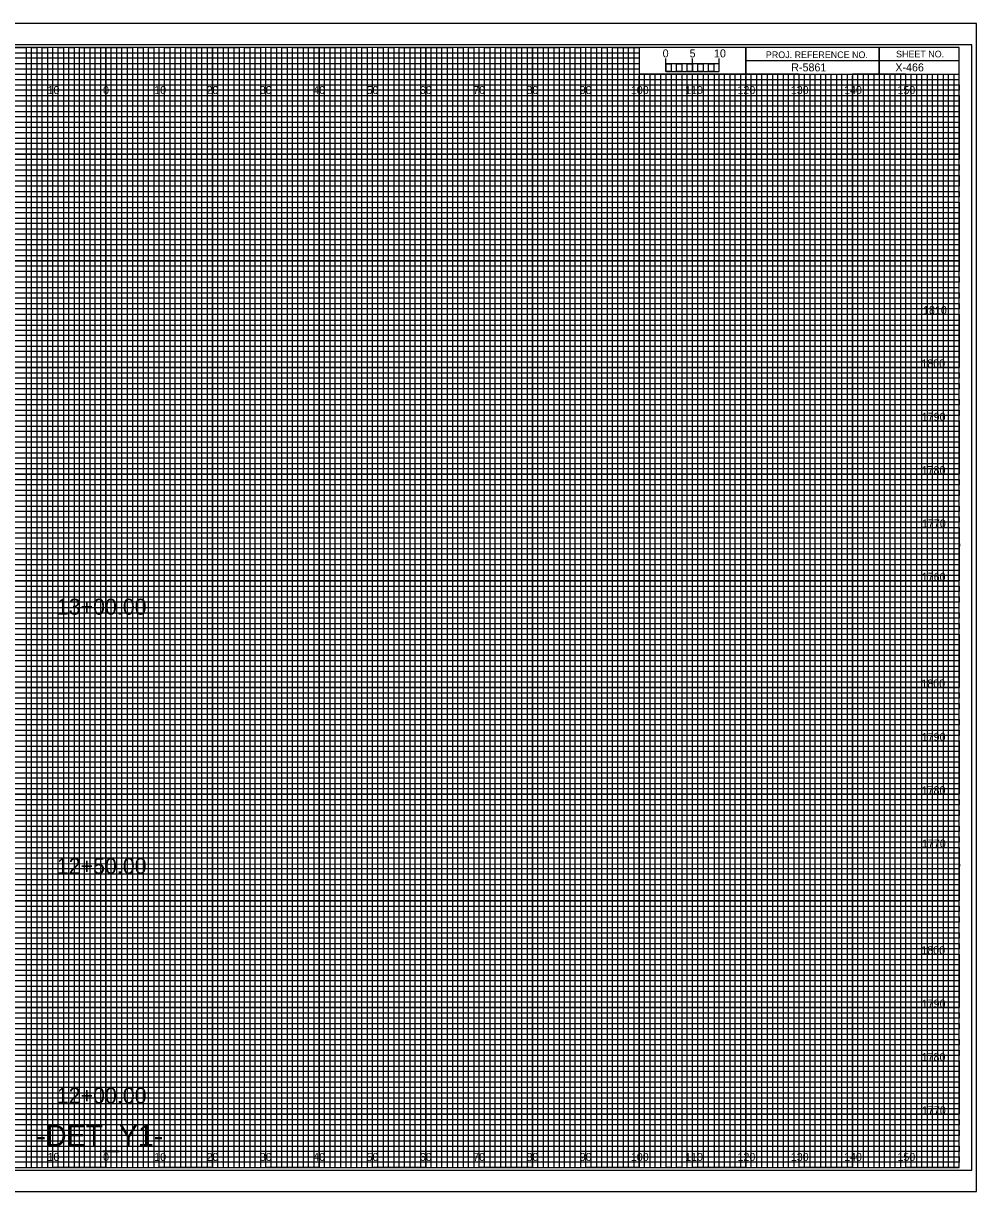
# Model space of a CAD drawing. Extents: x -13 to 323, y -5 to 434.
# Drawn here: x 144.5 to 323.3, y 215.5 to 434.5 of the extents above; entities that cross this region are included whole.
import ezdxf

# ---------------------------------------------------------------- set-up
doc = ezdxf.new("R2010")
doc.units = 0
for name, color, linetype in [('Old_Level_1', 7, 'Continuous'), ('Old_Level_62', 7, 'Continuous'), ('Pattern 1', 7, 'Continuous'), ('Pattern 18', 7, 'Continuous'), ('Pattern 4', 7, 'Continuous'), ('Pattern 5', 7, 'Continuous'), ('Prop Dimension', 7, 'Continuous'), ('Prop Horizontal Alignment', 7, 'Continuous'), ('Prop PHM Label Text', 7, 'Continuous'), ('Prop PHM Label Text White', 7, 'Continuous'), ('Prop PHM Roadway Shape', 7, 'Continuous'), ('Prop PHM White Shape', 7, 'Continuous'), ('Scratch_Level_0', 7, 'Continuous'), ('Scratch_Level_2', 7, 'Continuous'), ('Scratch_Level_3', 7, 'Continuous'), ('Scratch_Level_5', 7, 'Continuous'), ('Scratch_Level_6', 7, 'Continuous')]:
    doc.layers.add(name, color=color, linetype=linetype)

msp = doc.modelspace()

# ---------------------------------------------------------------- linework, layer by layer
at = {"layer": 'Old_Level_62'}
for p, q in [((0, 429), (260, 429)), ((260, 427.98), (0, 427.98)), ((260, 429), (260, 427.98)), ((0, 427), (260, 427)), ((260, 425.89), (0, 425.89)), ((260, 427), (260, 425.89)), ((0, 424), (320, 424))]:
    msp.add_line(p, q, dxfattribs=at)
for points in [[(0, 423), (270, 423), (320, 423), (320, 422), (0, 422)], [(0, 421), (320, 421), (320, 419), (0, 419)], [(0, 418), (320, 418), (320, 417), (0, 416.98)], [(0, 416), (320, 416), (320, 414), (0, 414)], [(0, 413), (320, 413), (320, 412), (0, 412)], [(0, 411), (320, 411), (320, 409), (0, 409)], [(0, 408), (320, 408), (320, 407), (0, 407)], [(0, 406), (320, 406), (320, 404), (0, 404)], [(0, 403), (320, 403), (320, 402), (0, 402)], [(0, 401), (320, 401), (320, 399), (0, 399)], [(0, 398), (320, 398), (320, 397), (0, 397)], [(0, 396), (320, 396), (320, 393.95), (320, 393), (320, 392), (0, 392)], [(0, 394), (320, 394), (320, 393), (0, 393)], [(0, 391), (320, 391), (320, 389), (0, 389.03)], [(0, 389.03), (320, 389), (320, 388), (0, 388)], [(0, 387), (320, 387), (320, 386), (0, 386)], [(0, 384), (320, 384), (320, 383), (0, 383)], [(0, 382), (320, 382), (320, 381), (0, 381)], [(-0.07, 378.89), (320, 378.89), (320, 377.88), (-0.07, 377.88)], [(0, 377), (320, 377), (320, 376), (0, 376)], [(0, 374), (320, 374), (320, 373), (0, 373)], [(0, 372), (320, 372), (320, 371), (0, 371)], [(0, 369), (320, 369), (320, 368), (0, 368)], [(0, 367), (320, 367), (320, 366), (0, 366)], [(0, 364), (320, 364), (320, 363), (0, 363)], [(0, 362), (320, 362), (320, 361), (0, 361)], [(0, 359), (320, 359), (319.99, 357.98), (0, 358)], [(0, 357), (320, 357), (320, 356), (0, 356)], [(0, 354), (320, 354), (320, 353), (0, 353)], [(0, 352), (320, 352), (320, 351), (0, 351)], [(0, 349), (320, 349), (320, 348), (0, 348)], [(0, 347), (320, 347), (320, 346), (0, 346)], [(0, 344), (320, 344), (320, 343), (0, 343)], [(0, 342), (320, 342), (320, 341), (0, 341)], [(0, 339), (320, 339), (320, 338), (0, 338)], [(0, 336.99), (320.07, 336.91), (320, 336), (0, 336)], [(0, 334), (320, 334), (320, 333), (0, 333)], [(0, 332), (320, 332), (320, 331), (0, 331)], [(0, 329), (320, 329), (320, 328), (0, 328)], [(0, 327), (320, 327), (320, 326), (0, 326)], [(0, 324), (320, 324), (320, 323), (0, 323)], [(0, 322), (320, 322), (320, 321), (0, 321)], [(0, 319), (320, 319), (320, 318), (0, 318)], [(0, 317), (320, 317), (320, 316), (0, 316)], [(0, 314), (320, 314), (320, 313), (0, 313)], [(0, 312), (320, 312), (320, 311), (0, 311)], [(0, 309), (320, 309), (320, 308), (0, 308)], [(0, 307), (320, 307), (320, 306), (0, 306)], [(0, 304), (320, 304), (320, 303), (0, 303)], [(0, 302), (320, 302), (320, 301), (0, 301)], [(0, 299), (320, 299), (319.99, 297.98), (0, 298)], [(0, 297), (320, 297), (320, 296), (0, 296)], [(0, 294), (320, 294), (320, 293), (0, 293)], [(0, 292), (320, 292), (320, 291), (0, 291)], [(0, 289), (320, 289), (320, 288), (0, 288)], [(0, 287), (320, 287), (320, 286), (0, 286)], [(0, 284), (320, 284), (320, 283), (0, 283)], [(0, 282), (320, 282), (320, 281), (0, 281)], [(0, 279), (320, 279), (320, 278), (0, 278)], [(0, 276.99), (320.07, 276.91), (320, 276), (0, 276)], [(0, 274), (320, 274), (320, 273), (0, 273)], [(0, 272), (320, 272), (320, 271), (0, 271)], [(0, 269), (320, 269), (320, 268), (0, 268)], [(0, 267), (320, 267), (320, 266), (0, 266)], [(0, 264), (320, 264), (320, 263), (0, 263)], [(0, 262), (320, 262), (320, 261), (0, 261)], [(0, 259), (320, 259), (320, 258), (0, 258)], [(0, 257), (320, 257), (320, 256), (0, 256)], [(0, 254), (320, 254), (320, 253), (0, 253)], [(0, 252), (320, 252), (320, 251), (0, 251)], [(0, 249), (320, 249), (320, 248), (0, 248)], [(0, 247), (320, 247), (320, 246), (0, 246)], [(0, 244), (320, 244), (320, 243), (0, 243)], [(0, 242), (320, 242), (320, 241), (0, 241)], [(0, 239), (320, 239), (320, 238), (0, 238)], [(0, 237), (320, 237), (320, 236), (0, 236)], [(0, 234), (320, 234), (320, 233), (0, 233)], [(0, 232), (320, 232), (320, 231), (0, 231)], [(0, 229), (320, 229), (320, 228), (0, 228)], [(0, 227), (320, 227), (320, 226), (0, 226)], [(0, 224), (320, 224), (320, 223), (0, 223)], [(0, 222), (320, 222), (320, 221), (0, 221)]]:
    msp.add_lwpolyline(points, dxfattribs=at)
at = {"layer": 'Pattern 1'}
for p, q in [((323.3, 434.5), (-13.4, 434.5)), ((-13.4, 215.5), (323.3, 215.5))]:
    msp.add_line(p, q, dxfattribs=at)
at = {"layer": 'Pattern 18'}
for p, q in [((265, 425.49), (265, 427.9)), ((265, 426.9), (265, 427.9)), ((270, 425.49), (270, 427.9)), ((275, 425.49), (275, 427.9)), ((275, 426.9), (275, 427.9))]:
    msp.add_line(p, q, dxfattribs=at)
for points in [[(275, 426.9), (265, 426.9), (265, 425.49), (275, 425.49)], [(265, 426.9), (266, 426.9), (266, 425.49), (265, 425.49)], [(267, 426.9), (268, 426.9), (268, 425.49), (267, 425.49)], [(269, 426.9), (270, 426.9), (270, 425.49), (269, 425.49)], [(271, 426.9), (272, 426.9), (272, 425.49), (271, 425.49)], [(273, 426.9), (274, 426.9), (274, 425.49), (273, 425.49)]]:
    msp.add_lwpolyline(points, close=True, dxfattribs=at)
at = {"layer": 'Pattern 4'}
for points in [[(135, 430), (145, 430), (145, 220), (155, 220), (155, 430), (165, 430), (165, 220), (175, 220), (175, 430), (185, 430), (185, 220), (195, 220), (195, 430), (205, 430), (205, 220), (215, 220), (215, 430), (225, 430), (225, 220), (235, 220), (235, 430), (245, 430), (245, 220), (255, 220), (255, 430), (259.93, 430), (260, 430), (260, 425), (264.99, 425), (264.99, 220), (275, 220), (275, 425), (285, 425), (285, 220), (295, 220), (295, 425), (305, 425), (305, 220), (315, 220), (315, 425)], [(0, 425), (275, 425)], [(0, 405), (320, 405), (320, 415), (0, 415)], [(0, 385), (320, 385), (320, 395), (0, 395)], [(0, 365), (320, 365), (320, 375), (0, 375)], [(0, 345), (320, 345), (320, 355), (0, 355)], [(0, 325), (320, 325), (320, 335), (0, 335)], [(0, 305), (320, 305), (320, 315), (0, 315)], [(0, 285), (320, 285), (320, 295), (0, 295)], [(0, 265), (320, 265), (320, 275), (0, 275)], [(0, 245), (320, 245), (320, 255), (0, 255)], [(0, 225), (320, 225), (320, 235), (0, 235)]]:
    msp.add_lwpolyline(points, dxfattribs=at)
at = {"layer": 'Pattern 5'}
for p, q in [((150, 220), (150, 430)), ((160, 220), (160, 430)), ((170, 220), (170, 430)), ((180, 220), (180, 430)), ((190, 220), (190, 430)), ((200, 220), (200, 430)), ((210, 220), (210, 430)), ((220, 220), (220, 430)), ((230, 220), (230, 430)), ((240, 220), (240, 430)), ((250, 220), (250, 430)), ((260, 220), (260, 424.69)), ((270, 220), (270, 424.69)), ((280, 220), (280, 424.69)), ((290, 220), (290, 424.69)), ((300, 220), (300, 424.69)), ((310, 220), (310, 424.69)), ((0, 420), (320, 420)), ((0, 410), (320, 410)), ((0, 400), (320, 400)), ((0, 390), (320, 390)), ((0, 380), (320, 380)), ((0, 370), (320, 370)), ((0, 360), (320, 360)), ((0, 350), (320, 350)), ((0, 340), (320, 340)), ((0, 330), (320, 330)), ((0, 320), (320, 320)), ((0, 310), (320, 310)), ((0, 300), (320, 300)), ((0, 290), (320, 290)), ((0, 280), (320, 280)), ((0, 270), (320, 270)), ((0, 260), (320, 260)), ((0, 250), (320, 250)), ((0, 240), (320, 240)), ((0, 230), (320, 230))]:
    msp.add_line(p, q, dxfattribs=at)
at = {"layer": 'Prop Dimension'}
for p, q in [((305, 430), (305, 425)), ((305, 425), (305, 430)), ((280, 427.5), (280, 425)), ((320, 427.49), (280, 427.49)), ((280, 425), (320, 425))]:
    msp.add_line(p, q, dxfattribs=at)
for points in [[(320, 430), (0, 430), (0, 220), (320, 220)], [(280, 430), (260, 430), (260, 425.03), (280, 425.03)], [(320, 430), (280, 430), (280, 425), (320, 425)]]:
    msp.add_lwpolyline(points, close=True, dxfattribs=at)
at = {"layer": 'Prop Horizontal Alignment'}
for p, q in [((150, 430), (140, 430)), ((150, 220), (150, 430)), ((170, 430), (160, 430)), ((160, 430), (160, 220)), ((170, 220), (170, 430)), ((190, 430), (180, 430)), ((180, 430), (180, 220)), ((190, 220), (190, 430)), ((210, 430), (200, 430)), ((200, 430), (200, 220)), ((210, 220), (210, 430)), ((230, 430), (220, 430)), ((220, 430), (220, 220)), ((230, 220), (230, 430)), ((250, 430), (240, 430)), ((240, 430), (240, 220)), ((250, 220), (250, 430)), ((260, 430), (260, 220)), ((270, 220), (270, 425)), ((290, 425), (280, 425)), ((280, 425), (280, 220)), ((290, 220), (290, 425)), ((310, 425), (300, 425)), ((300, 425), (300, 220)), ((310, 220), (310, 425)), ((160, 220), (150, 220)), ((180, 220), (170, 220)), ((200, 220), (190, 220)), ((220, 220), (210, 220)), ((240, 220), (230, 220)), ((260, 220), (250, 220)), ((280, 220), (270, 220)), ((300, 220), (290, 220)), ((320, 220), (310, 220)), ((320, 220), (320, 220))]:
    msp.add_line(p, q, dxfattribs=at)
for points in [[(0, 420), (320, 420), (320, 410), (0, 410)], [(0, 400), (320, 400), (320, 390), (0, 390)], [(0, 380), (320, 380), (320, 370), (0, 370)], [(0, 360), (320, 360), (320, 350), (0, 350)], [(0, 340), (320, 340), (320, 330), (0, 330)], [(0, 320), (320, 320), (320, 310), (0, 310)], [(0, 300), (320, 300), (320, 290), (0, 290)], [(0, 280), (320, 280), (320, 270), (0, 270)], [(0, 260), (320, 260), (320, 250), (0, 250)], [(0, 240), (320, 240), (320, 230), (0, 230)]]:
    msp.add_lwpolyline(points, dxfattribs=at)
at = {"layer": 'Prop PHM Label Text'}
for p, q in [((267, 425), (266.01, 425)), ((266.01, 425), (266.01, 220)), ((267, 220), (267, 425)), ((269, 425), (268, 425)), ((268, 425), (268, 220)), ((269, 220), (269, 425)), ((266.01, 220), (265, 220)), ((268, 220), (267, 220))]:
    msp.add_line(p, q, dxfattribs=at)
for points in [[(145, 220), (146, 220), (146, 430), (147, 430), (147, 220)], [(147, 220), (148, 220), (148, 430), (149, 430), (149, 220)], [(150, 220), (151, 220), (151, 430), (152, 430), (152, 220)], [(152, 220), (153, 220), (153, 430), (154, 430), (154, 220)], [(155, 220), (156, 220), (156, 430), (157, 430), (157, 220)], [(157, 220), (158, 220), (158, 430), (159, 430), (159, 220)], [(160, 220), (161, 220), (161, 430), (162, 430), (162, 220)], [(162, 220), (163, 220), (163, 430), (164, 430), (164, 220)], [(165, 220), (166, 220), (166, 430), (167, 430), (167, 220)], [(167, 220), (168, 220), (168, 430), (169, 430), (169, 220)], [(170, 220), (171, 220), (171, 430), (172, 430), (172, 220)], [(172, 220), (173, 220), (173, 430), (174, 430), (174, 220)], [(175, 220), (176, 220), (176, 430), (177, 430), (177, 220)], [(177, 220), (178, 220), (178, 430), (179, 430), (179, 220)], [(180, 220), (181, 220), (181, 430), (182, 430), (182, 220)], [(182, 220), (183, 220), (183, 430), (184, 430), (184, 220)], [(185, 220), (186, 220), (186, 430), (187, 430), (187, 220)], [(187, 220), (188, 220), (188, 430), (189, 430), (189, 220)], [(190, 220), (191, 220), (191, 430), (192, 430), (192, 220)], [(192, 220), (193, 220), (193, 430), (194, 430), (194, 220)], [(195, 220), (196, 220), (196, 430), (197, 430), (197, 220)], [(197, 220), (198, 220), (198, 430), (199, 430), (199, 220)], [(200, 220), (201, 220), (201, 430), (202, 430), (202, 220)], [(202, 220), (203, 220), (203, 430), (204, 430), (204, 220)], [(205, 220), (206, 220), (206, 430), (207, 430), (207, 220)], [(207, 220), (208, 220), (208, 430), (209, 430), (209, 220)], [(210, 220), (211, 220), (211, 430), (212, 430), (212, 220)], [(212, 220), (213, 220), (213, 430), (214, 430), (214, 220)], [(215, 220), (216, 220), (216, 430), (217, 430), (217, 220)], [(217, 220), (218, 220), (218, 430), (219, 430), (219, 220)], [(220, 220), (221, 220), (221, 430), (222, 430), (222, 220)], [(222, 220), (223, 220), (223, 430), (224, 430), (224, 220)], [(225, 220), (226, 220), (226, 430), (227, 430), (227, 220)], [(227, 220), (228, 220), (228, 430), (229, 430), (229, 220)], [(230, 220), (231, 220), (231, 430), (232, 430), (232, 220)], [(232, 220), (233, 220), (233, 430), (234, 430), (234, 220)], [(235, 220), (236, 220), (236, 430), (237, 430), (237, 220)], [(237, 220), (238, 220), (238, 430), (239, 430), (239, 220)], [(240, 220), (241, 220), (241, 430), (242, 430), (242, 220)], [(242, 220), (243, 220), (243, 430), (244, 430), (244, 220)], [(245, 220), (246, 220), (246, 430), (247, 430), (247, 220)], [(247, 220), (248, 220), (248, 430), (249, 430), (249, 220)], [(250, 220), (251, 220), (251, 430), (252, 430), (252, 220)], [(252, 220), (253, 220), (253, 430), (254, 430), (254, 220)], [(255, 220), (256, 220), (256, 430), (257, 430), (257, 220)], [(257, 220), (258, 220), (258, 430), (259, 430), (259, 220)], [(260, 220), (261, 220), (261, 425), (262.02, 425), (262.02, 220)], [(262, 220), (263, 220), (263, 425), (263.99, 425), (263.99, 220)], [(270, 220), (270.98, 220), (270.98, 425), (272, 425), (272, 220)], [(272, 220), (273, 220), (273, 425), (274.05, 425), (274.05, 220)], [(275, 220), (276, 220), (276, 425), (277, 425), (277, 220)], [(277, 220), (278, 220), (278, 425), (279, 425), (279, 220)], [(280, 220), (281, 220), (281, 425), (282, 425), (282, 220)], [(282, 220), (283, 220), (283, 425), (284, 425), (284, 220)], [(285, 220), (286, 220), (286, 425), (287, 425), (287, 220)], [(287, 220), (288, 220), (288, 425), (289, 425), (289, 220)], [(290, 220), (291, 220), (291, 425), (292, 425), (292, 220)], [(292, 220), (293, 220), (293, 425), (294, 425), (294, 220)], [(295, 220), (296, 220), (296, 425), (297, 425), (297, 220)], [(297, 220), (298, 220), (298, 425), (299, 425), (299, 220)], [(300, 220), (301, 220), (301, 425), (302, 425), (302, 220)], [(302, 220), (303, 220), (303, 425), (304, 425), (304, 220)], [(305, 220), (306, 220), (306, 425), (307, 425), (307, 220)], [(307, 220), (308, 220), (308, 425), (309, 425), (309, 220)], [(310, 220), (311, 220), (311, 425), (312, 425), (312, 220)], [(312, 220), (313, 220), (313, 425), (314, 425), (314, 220)], [(315, 220), (316, 220), (316, 425), (317, 425), (317, 220)], [(317, 220), (318, 220), (318, 425), (319, 425), (319, 220)]]:
    msp.add_lwpolyline(points, dxfattribs=at)
at = {"layer": 'Scratch_Level_0'}
msp.add_lwpolyline([(-10.8, 219.5), (322.4, 219.5), (322.4, 430.5), (-10.8, 430.5)], close=True, dxfattribs=at)
at = {"layer": 'Scratch_Level_5'}
msp.add_lwpolyline([(-13.4, 215.5), (323.3, 215.5), (323.3, 434.5), (-13.4, 434.5)], close=True, dxfattribs=at)

# ---------------------------------------------------------------- texts
at = {"layer": 'Old_Level_1'}
msp.add_text('-DET_Y1-', height=4, dxfattribs=at).set_placement((146.97, 224))
at = {"layer": 'Pattern 18'}
msp.add_text('0', height=1.5, dxfattribs=at).set_placement((264.41, 428.12))
at = {"layer": 'Prop Dimension'}
for s, p in [('PROJ. REFERENCE NO.', (283.77, 427.99)), ('SHEET NO.', (308.19, 428.12))]:
    msp.add_text(s, height=1.25, dxfattribs=at).set_placement(p)
at = {"layer": 'Prop PHM Label Text White'}
for s, p in [('13+00.00', (150.77, 323.65)), ('12+50.00', (150.77, 275.05)), ('12+00.00', (150.77, 232.02))]:
    msp.add_text(s, height=3, dxfattribs=at).set_placement(p)
at = {"layer": 'Prop PHM Roadway Shape'}
msp.add_text('X-466', height=1.5, dxfattribs=at).set_placement((308.05, 425.5))
at = {"layer": 'Prop PHM White Shape'}
msp.add_text('R-5861', height=1.5, dxfattribs=at).set_placement((288.53, 425.5))
at = {"layer": 'Scratch_Level_2'}
for s, p in [('1810', (313.25, 380)), ('1800', (312.92, 370)), ('1790', (313, 360)), ('1780', (312.98, 350)), ('1770', (313.04, 340)), ('1760', (313, 330)), ('1800', (312.92, 310)), ('1790', (313, 300)), ('1780', (312.98, 290)), ('1770', (313.04, 280)), ('1800', (312.92, 260)), ('1790', (313, 250)), ('1780', (312.98, 240)), ('1770', (313.04, 230))]:
    msp.add_text(s, height=1.5, dxfattribs=at).set_placement(p)
at = {"layer": 'Scratch_Level_3'}
for s, p in [('10', (149.04, 421.25)), ('0', (159.45, 421.25)), ('0', (159.45, 421.25)), ('10', (169.04, 421.25)), ('20', (178.86, 421.25)), ('30', (188.86, 421.25)), ('40', (198.86, 421.25)), ('50', (208.86, 421.25)), ('60', (218.86, 421.25)), ('70', (228.86, 421.25)), ('80', (238.86, 421.25)), ('90', (248.86, 421.25)), ('100', (258.44, 421.25)), ('110', (268.62, 421.25)), ('120', (278.44, 421.25)), ('130', (288.44, 421.25)), ('140', (298.44, 421.25)), ('150', (308.44, 421.25)), ('10', (149.04, 221.25)), ('0', (159.45, 221.25)), ('0', (159.45, 221.25)), ('10', (169.04, 221.25)), ('20', (178.86, 221.25)), ('30', (188.86, 221.25)), ('40', (198.86, 221.25)), ('50', (208.86, 221.25)), ('60', (218.86, 221.25)), ('70', (228.86, 221.25)), ('80', (238.86, 221.25)), ('90', (248.86, 221.25)), ('100', (258.44, 221.25)), ('110', (268.62, 221.25)), ('120', (278.44, 221.25)), ('130', (288.44, 221.25)), ('140', (298.44, 221.25)), ('150', (308.44, 221.25))]:
    msp.add_text(s, height=1.5, dxfattribs=at).set_placement(p)
at = {"layer": 'Scratch_Level_6'}
for s, p in [('5', (269.47, 428.12)), ('10', (274.04, 428.12))]:
    msp.add_text(s, height=1.5, dxfattribs=at).set_placement(p)

doc.saveas('drawing.dxf')
